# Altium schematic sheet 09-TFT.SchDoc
size A4
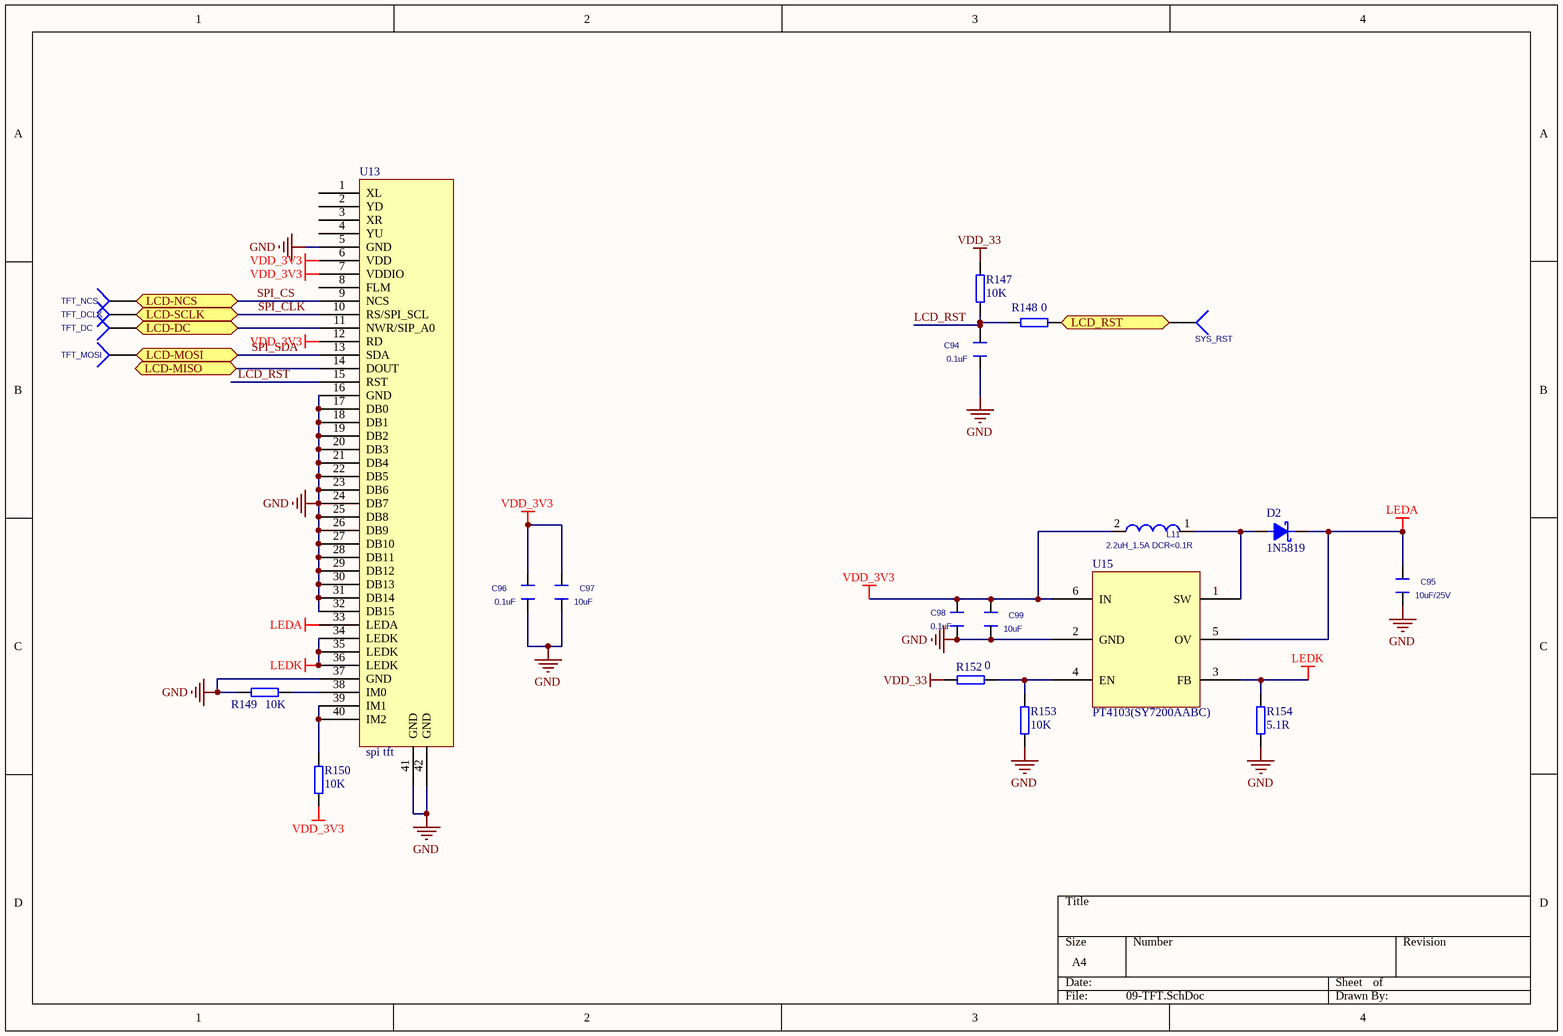
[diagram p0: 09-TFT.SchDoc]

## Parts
C94  0.1uF  [C0402]
C95  10uF/25V  [C0603]
C96  0.1uF  [C0402]
C97  10uF  [C0603]
C98  0.1uF  [C0402]
C99  10uF  [C0603]
D2  1N5819  [SOD-123]
L11  2.2uH_1.5A DCR<0.1R  [L-4.0S]
R147  10K  [R0402]
R148  0  [R0402]
R149  10K  [R0402]
R150  10K  [R0402]
R152  0  [R0402]
R153  10K  [R0402]
R154  5.1R  [R0402]
SYS_RST  (no value)  [test]
TFT_DC  (no value)  [test]
TFT_DCLK  (no value)  [test]
TFT_MOSI  (no value)  [test]
TFT_NCS  (no value)  [test]
U13  spi tft  [FPC-40-0.5-up]
U15  PT4103(SY7200AABC)  [SOT23-6]

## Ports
LCD-DC (bidir), LCD-MISO (bidir), LCD-MOSI (bidir), LCD-NCS (bidir), LCD-SCLK (bidir), LCD_RST (bidir)

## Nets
GND: C94.2 C95.2 C96.2 C97.2 C98.2 C99.2 R149.1 R153.2 R154.2 U13.5(GND) U13.16(GND) U13.17(DB0) U13.18(DB1) U13.19(DB2) U13.20(DB3) U13.21(DB4) U13.22(DB5) U13.23(DB6) U13.24(DB7) U13.25(DB8) U13.26(DB9) U13.27(DB10) U13.28(DB11) U13.29(DB12) U13.30(DB13) U13.31(DB14) U13.32(DB15) U13.37(GND) U13.41(GND) U13.42(GND) U15.2(GND)
LEDA: C95.1 D2.2(K) U13.33(LEDA) U15.5(OV)
LEDK: R154.1 U13.34(LEDK) U13.35(LEDK) U13.36(LEDK) U15.3(FB)
VDD_3V3: C96.1 C97.1 C98.1 C99.1 L11.2 R150.2 U13.6(VDD) U13.7(VDDIO) U13.12(RD) U15.6(IN)
VDD_33: R147.1 R152.2
LCD-DC: TFT_DC.1(A) U13.11(NWR/SIP_A0) ; port LCD-DC
LCD-MISO: U13.14(DOUT) ; port LCD-MISO
LCD_RST: C94.1 R147.2 R148.1 U13.15(RST)
LCD_RST: R148.2 SYS_RST.1(A) ; port LCD_RST  [a separate net that carries the same name]
SPI_CLK: TFT_DCLK.1(A) U13.10(RS/SPI_SCL) ; port LCD-SCLK
SPI_CS: TFT_NCS.1(A) U13.9(NCS) ; port LCD-NCS
SPI_SDA: TFT_MOSI.1(A) U13.13(SDA) ; port LCD-MOSI
NetD2_1: D2.1(A) L11.1 U15.1(SW)
NetR149_2: R149.2 U13.38(IM0)
NetR150_1: R150.1 U13.39(IM1) U13.40(IM2)
NetR152_1: R152.1 R153.1 U15.4(EN)

Not connected (* = marked no-connect by the designer): U13 1(XL) 2(YD) 3(XR) 4(YU) 8(FLM)

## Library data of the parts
C94 C96 C98 = CAPACITOR_1: ROOM: DCDC; PAGE: 5
C95 C97 C99 = CAPACITOR_3: ROOM: DCDC; PAGE: 5
D2 = 二极管(肖特基): Diode Schottky
L11 = INDUCTOR_Dup1: ROOM: DCDC; PAGE: 5
R147-R150 R152-R154 = 电阻Ω: Resistor
SYS_RST TFT_DC TFT_DCLK TFT_MOSI TFT_NCS = Test_Jack
U15 = PT4103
